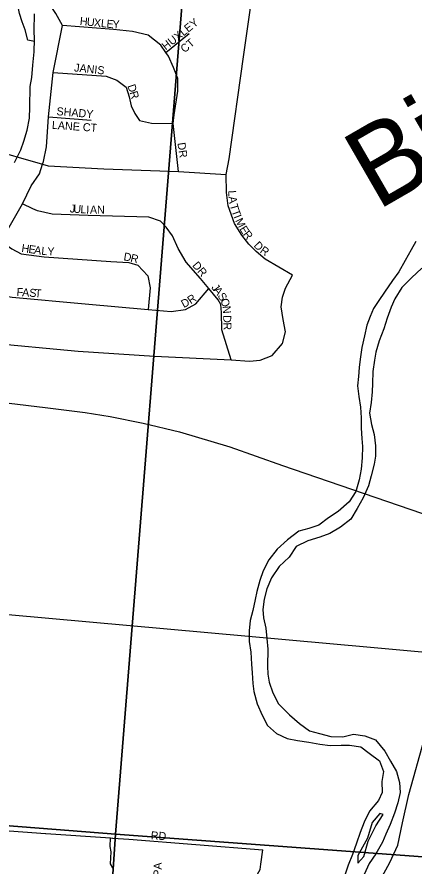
# Model space of a CAD drawing. Extents: x 0 to 34, y 0 to 22.
# Drawn here: x 7.208 to 7.677, y 18.975 to 19.979 of the extents above; entities that cross this region are included whole.
import ezdxf

# ---------------------------------------------------------------- set-up
doc = ezdxf.new("R2010")
doc.units = 0
for name, color, linetype in [('GM_X_City_Street', 7, 'Continuous'), ('GM_X_City_Street_Text', 7, 'Continuous'), ('GM_X_Interstate_Route', 7, 'Continuous'), ('GM_X_Major_River', 7, 'Continuous'), ('GM_X_Major_River_Text', 7, 'Continuous'), ('GM_X_Minor_River', 7, 'Continuous'), ('GM_X_Rail_Line', 7, 'Continuous'), ('GM_X_Section', 7, 'Continuous')]:
    doc.layers.add(name, color=color, linetype=linetype)

msp = doc.modelspace()

# ---------------------------------------------------------------- linework, layer by layer
at = {"layer": 'GM_X_City_Street'}
for points in [[(7.1281, 19.5971), (7.1279, 19.603), (7.1353, 19.62), (7.1431, 19.6374), (7.157, 19.6605), (7.1887, 19.7137), (7.2139, 19.7579), (7.2244, 19.7791), (7.2341, 19.7934), (7.2378, 19.8047), (7.2388, 19.8078), (7.2424, 19.8252), (7.2447, 19.8606), (7.2502, 19.9133), (7.2613, 19.9689), (7.2536, 19.9831), (7.2478, 19.9914), (7.2448, 19.9998), (7.2431, 20.009), (7.2435, 20.0157)], [(7.4755, 19.9318), (7.4865, 20.0093)], [(7.3984, 19.7959), (7.3921, 19.8528), (7.3935, 19.8631), (7.3977, 19.8912), (7.3978, 19.906), (7.3926, 19.919), (7.3867, 19.9327), (7.3837, 19.937), (7.3778, 19.9454), (7.3627, 19.9573), (7.3442, 19.9617), (7.3218, 19.9639), (7.2613, 19.9689)], [(7.3837, 19.937), (7.4113, 19.9594)], [(7.5335, 19.6736), (7.5009, 19.6924), (7.4903, 19.7013), (7.4817, 19.7102), (7.4733, 19.7206), (7.4649, 19.7344), (7.4574, 19.7554), (7.4555, 19.7712), (7.4551, 19.7926), (7.4585, 19.8111), (7.4755, 19.9318)], [(7.2502, 19.9133), (7.3132, 19.9088), (7.3257, 19.9041), (7.3366, 19.8957), (7.3402, 19.8846), (7.3424, 19.8739), (7.3469, 19.8648), (7.3525, 19.8563), (7.3665, 19.8531), (7.3921, 19.8528)], [(7.2447, 19.8606), (7.2951, 19.857)], [(7.1714, 19.8238), (7.2378, 19.8047), (7.2444, 19.8028), (7.3101, 19.7994), (7.3984, 19.7959), (7.4551, 19.7926)], [(7.4345, 19.6578), (7.4244, 19.6697), (7.4075, 19.6889), (7.3982, 19.7049), (7.3915, 19.7198), (7.3841, 19.7302), (7.3773, 19.7375), (7.3633, 19.7422), (7.2916, 19.7441), (7.2491, 19.7457), (7.2317, 19.7497), (7.2264, 19.7521), (7.2139, 19.7579)], [(7.1887, 19.7137), (7.2015, 19.7045), (7.2125, 19.6986), (7.2398, 19.6953), (7.3187, 19.6898), (7.3399, 19.6885), (7.3505, 19.6853), (7.3621, 19.6726), (7.365, 19.6585), (7.3628, 19.6329)], [(7.1703, 19.5938), (7.2799, 19.5835), (7.3702, 19.5775), (7.4609, 19.5733), (7.4826, 19.5718), (7.495, 19.5728), (7.5093, 19.5783), (7.5217, 19.5926), (7.5251, 19.6064), (7.5222, 19.6212), (7.5199, 19.6361), (7.5217, 19.6474), (7.5251, 19.6581), (7.5335, 19.6736)], [(7.157, 19.6605), (7.1751, 19.6519), (7.2017, 19.6474), (7.2881, 19.6396), (7.3628, 19.6329), (7.3898, 19.6305), (7.4069, 19.633), (7.4191, 19.6397), (7.4345, 19.6578)], [(7.4609, 19.5733), (7.4499, 19.6089), (7.4493, 19.6295), (7.4487, 19.6386), (7.4453, 19.6443), (7.4345, 19.6578)], [(7.6191, 18.9248), (7.6485, 18.9786), (7.6581, 18.9994), (7.6635, 19.0256), (7.6709, 19.0594), (7.6896, 19.1255), (7.7061, 19.1787), (7.7276, 19.2464), (7.7314, 19.2566), (7.7409, 19.2661), (7.8255, 19.3496), (7.8945, 19.4177), (7.9025, 19.4324), (7.9079, 19.4465), (7.9083, 19.4486), (7.9086, 19.4514)], [(6.8177, 19.0455), (7.0758, 19.0249), (7.1282, 19.0212), (7.2414, 19.0132), (7.2417, 19.0132)], [(7.2417, 19.0132), (7.3181, 19.0078), (7.3203, 19.0077), (7.3207, 19.0076)], [(7.3208, 18.9725), (7.3183, 18.9771), (7.3189, 18.9915), (7.3179, 18.9976), (7.3181, 19.0078)], [(7.3207, 19.0076), (7.34, 19.0063), (7.4982, 18.9939)], [(7.4283, 18.8473), (7.4652, 18.9179), (7.4872, 18.9566), (7.495, 18.9705), (7.4959, 18.9769), (7.4982, 18.9939)]]:
    msp.add_lwpolyline(points, dxfattribs=at)
at = {"layer": 'GM_X_Interstate_Route'}
msp.add_lwpolyline([(6.8515, 19.5006), (6.856, 19.501), (6.9003, 19.5063), (7.0139, 19.5201), (7.0525, 19.5234), (7.0975, 19.5249), (7.1506, 19.5247), (7.1982, 19.5221), (7.2409, 19.5171), (7.2883, 19.5109), (7.3176, 19.5063), (7.3568, 19.4984), (7.3997, 19.4881), (7.4592, 19.4703), (7.5217, 19.4482), (7.6858, 19.3921), (7.7744, 19.3608), (7.8161, 19.3516), (7.8255, 19.3496)], dxfattribs=at)
at = {"layer": 'GM_X_Major_River'}
for points in [[(7.6794, 19.7131), (7.6737, 19.7033), (7.6665, 19.6908), (7.6593, 19.6775), (7.6517, 19.6672), (7.6422, 19.6532), (7.6357, 19.6437), (7.6293, 19.6339), (7.6251, 19.6244), (7.6213, 19.6145), (7.6186, 19.6016), (7.6156, 19.588), (7.6133, 19.5743), (7.6121, 19.5644), (7.6114, 19.5538), (7.6102, 19.5424), (7.6117, 19.5299), (7.6139, 19.5174), (7.6147, 19.5049), (7.6147, 19.4927), (7.6154, 19.4802), (7.6161, 19.4707), (7.6157, 19.4574), (7.6146, 19.4441), (7.6123, 19.4312), (7.6085, 19.4176), (7.6005, 19.4054), (7.5876, 19.3941), (7.5759, 19.3865), (7.5645, 19.3778), (7.5528, 19.374), (7.5407, 19.3706), (7.5274, 19.3604), (7.5153, 19.3494), (7.5054, 19.3369), (7.4986, 19.3236), (7.4948, 19.3122), (7.4914, 19.2993), (7.4894, 19.2898), (7.4864, 19.2769), (7.4833, 19.2652), (7.4822, 19.2527), (7.4822, 19.2401), (7.484, 19.2276), (7.4848, 19.2132), (7.4855, 19.2033), (7.4866, 19.1904), (7.4877, 19.1809), (7.4915, 19.1665), (7.4975, 19.1532), (7.5039, 19.1407), (7.5145, 19.1312), (7.527, 19.1255), (7.5394, 19.1232), (7.5527, 19.1212), (7.5659, 19.1186), (7.578, 19.117), (7.5909, 19.1174), (7.6007, 19.1174), (7.6143, 19.1155), (7.6241, 19.1082), (7.6362, 19.0991), (7.6411, 19.0866), (7.6392, 19.0744), (7.6396, 19.0615), (7.635, 19.0521), (7.6244, 19.0396), (7.6183, 19.0263), (7.6134, 19.0141), (7.6092, 19.0016), (7.6043, 18.9883), (7.5993, 18.9755), (7.5951, 18.9637)], [(7.6865, 19.6816), (7.674, 19.6702), (7.6626, 19.6589), (7.6543, 19.6456), (7.6501, 19.6357), (7.6455, 19.6228), (7.6413, 19.6099), (7.636, 19.5959), (7.6318, 19.5823), (7.6303, 19.5728), (7.6284, 19.5595), (7.628, 19.5454), (7.6276, 19.5356), (7.6264, 19.5227), (7.6245, 19.5102), (7.6268, 19.4969), (7.6298, 19.4851), (7.6316, 19.4718), (7.6316, 19.4593), (7.6301, 19.4498), (7.6263, 19.4361), (7.6232, 19.4244), (7.6171, 19.4103), (7.6099, 19.3975), (7.6023, 19.3849), (7.5902, 19.3755), (7.5777, 19.3679), (7.5656, 19.3637), (7.5516, 19.3592), (7.5376, 19.3524), (7.5293, 19.3399), (7.5175, 19.3289), (7.5084, 19.3156), (7.5031, 19.3024), (7.4997, 19.2902), (7.4985, 19.2781), (7.4989, 19.2682), (7.5019, 19.256), (7.503, 19.2439), (7.5041, 19.231), (7.504, 19.2109), (7.5044, 19.2014), (7.5059, 19.1919), (7.51, 19.1794), (7.5168, 19.1665), (7.5297, 19.1535), (7.5418, 19.1433), (7.5535, 19.1345), (7.5652, 19.1315), (7.5788, 19.1277), (7.5928, 19.1276), (7.6057, 19.1307), (7.6189, 19.1287), (7.6317, 19.1238), (7.6427, 19.1105), (7.6495, 19.0987), (7.6563, 19.0866), (7.66, 19.0733), (7.6608, 19.0615), (7.6581, 19.0494), (7.6539, 19.0372), (7.649, 19.0236), (7.6436, 19.0122), (7.6398, 19.0027), (7.6319, 18.9891), (7.6239, 18.9777), (7.6182, 18.9644)], [(7.6107, 18.9781), (7.6179, 18.9857), (7.6228, 19.0039), (7.6319, 19.0221), (7.6407, 19.0354), (7.6365, 19.0369)], [(7.6365, 19.0369), (7.6278, 19.0259), (7.6221, 19.0077), (7.616, 18.9971), (7.6107, 18.9872), (7.6107, 18.9781)]]:
    msp.add_lwpolyline(points, dxfattribs=at)
at = {"layer": 'GM_X_Minor_River'}
for points in [[(7.2282, 19.9499), (7.2204, 19.9513), (7.217, 19.9635), (7.2137, 19.9733), (7.2103, 19.9829), (7.2078, 19.9965), (7.2063, 20.0075)], [(7.2047, 19.8067), (7.212, 19.8219), (7.2158, 19.8321), (7.2197, 19.845), (7.2224, 19.859), (7.2229, 19.8723), (7.223, 19.8966), (7.225, 19.9072), (7.2262, 19.922), (7.2278, 19.9376), (7.2283, 19.9524), (7.228, 19.963), (7.2281, 19.9824)]]:
    msp.add_lwpolyline(points, dxfattribs=at)
at = {"layer": 'GM_X_Rail_Line'}
msp.add_lwpolyline([(6.6636, 19.3159), (7.0524, 19.2852), (7.6258, 19.2334), (7.6994, 19.2269), (7.7338, 19.2217), (7.7924, 19.2016), (7.8578, 19.1642), (8.0007, 19.0761), (8.2969, 18.8979), (8.814, 18.5835), (9.2779, 18.3027), (9.4, 18.2291)], dxfattribs=at)
at = {"layer": 'GM_X_Section'}
for points in [[(6.8995, 20.0595), (7.4047, 20.0213), (7.324, 19.0124), (6.8218, 19.0519)], [(7.4047, 20.0213), (7.911, 19.983), (7.832, 18.9749), (7.324, 19.0124)], [(6.8218, 19.0519), (7.324, 19.0124), (7.2561, 17.997), (6.7511, 18.0375)], [(7.324, 19.0124), (7.832, 18.9749), (7.7594, 17.9553), (7.2561, 17.997)]]:
    msp.add_lwpolyline(points, close=True, dxfattribs=at)

# ---------------------------------------------------------------- texts
at = {"layer": 'GM_X_City_Street_Text'}
for s, rotation, p in [('H', 354.1981, (7.2815, 19.9695)), ('U', 354.1981, (7.2898, 19.9687)), ('X', 354.2206, (7.2981, 19.9678)), ('L', 354.197, (7.3064, 19.967)), ('E', 354.4643, (7.3131, 19.9663)), ('Y', 358.2956, (7.3204, 19.9656)), ('HUXLEY', 38.5013, (7.3835, 19.9391)), ('CT', 40.6039, (7.4058, 19.9359)), ('JANIS', 353.994, (7.2748, 19.9145)), ('D', 288.2276, (7.338, 19.8975)), ('R', 287.0063, (7.3406, 19.8896)), ('SHADY', 355.239, (7.254, 19.8628)), ('LANE CT', 356.0571, (7.2486, 19.8466)), ('DR', 278.9785, (7.3972, 19.8297)), ('L', 274.1284, (7.4572, 19.7734)), ('A', 277.5526, (7.4577, 19.7661)), ('J', 355.6683, (7.2698, 19.7478)), ('U', 355.6691, (7.2739, 19.7475)), ('L', 355.8871, (7.2823, 19.7469)), ('I', 357.8193, (7.2893, 19.7464)), ('A', 359.6662, (7.2938, 19.7462)), ('N', 359.9929, (7.3022, 19.7462)), ('T', 285.8061, (7.4591, 19.7564)), ('T', 289.918, (7.4611, 19.7493)), ('I', 290.9269, (7.4635, 19.7428)), ('M', 296.1067, (7.4653, 19.7381)), ('E', 301.6262, (7.4702, 19.7282)), ('R', 307.771, (7.4743, 19.7217)), ('D', 314.8918, (7.4869, 19.7078)), ('H', 351.8204, (7.2124, 19.701)), ('E', 351.8213, (7.2207, 19.6999)), ('A', 351.8204, (7.2273, 19.6989)), ('L', 354.669, (7.236, 19.6977)), ('Y', 359.3171, (7.2435, 19.697)), ('R', 325.3448, (7.4942, 19.7008)), ('D', 350.6024, (7.3331, 19.6911)), ('R', 345.846, (7.3411, 19.6897)), ('DR', 310.6039, (7.4143, 19.6847)), ('F', 355.848, (7.2068, 19.6491)), ('A', 355.9165, (7.2134, 19.6486)), ('S', 355.8988, (7.2218, 19.6481)), ('T', 355.9365, (7.2284, 19.6476)), ('J', 306.59, (7.4369, 19.6588)), ('A', 306.577, (7.4394, 19.6555)), ('D', 28.4221, (7.4048, 19.6344)), ('R', 34.7837, (7.4131, 19.6389)), ('S', 304.4705, (7.4443, 19.6488)), ('O', 291.1521, (7.4478, 19.6439)), ('N', 274.9669, (7.4506, 19.6368)), ('D', 270.5028, (7.4514, 19.6262)), ('R', 272.6894, (7.4515, 19.6174)), ('RD', 356.989, (7.3656, 19.0062)), ('CATALPA', 88.2125, (7.377, 18.921))]:
    msp.add_text(s, height=0.00947, rotation=rotation, dxfattribs=at).set_placement(p)
at = {"layer": 'GM_X_Major_River_Text'}
msp.add_text('Big', height=0.0947, rotation=30.0102, dxfattribs=at).set_placement((7.6335, 19.7493))

doc.saveas('drawing.dxf')
